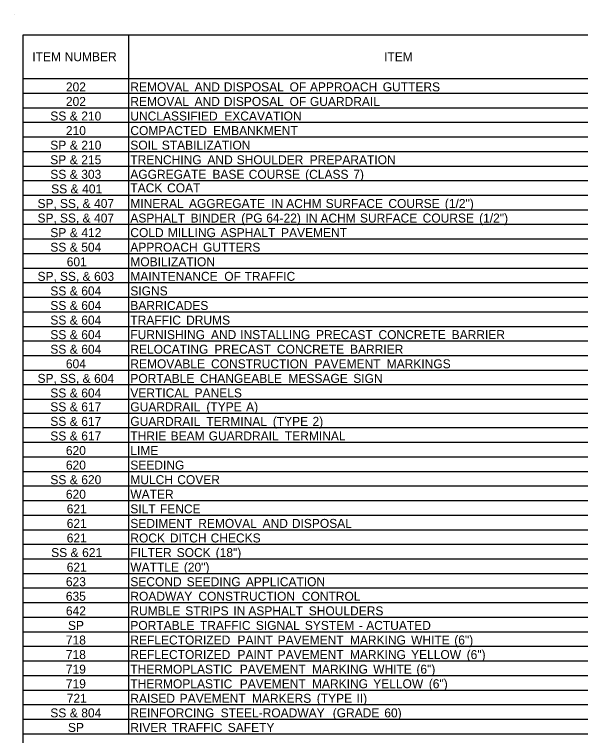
# Model space of a CAD drawing. Extents: x 544250 to 1930787, y -1948365 to 596640.
# Drawn here: x 557859.6 to 558238.2, y -1947939.8 to -1947457.4 of the extents above; entities that cross this region are included whole.
import ezdxf

# ---------------------------------------------------------------- set-up
doc = ezdxf.new("R2010")
doc.units = 0
doc.layers.add('Default', color=7, linetype='Continuous')

msp = doc.modelspace()

# ---------------------------------------------------------------- linework, layer by layer
at = {"layer": 'Default'}
for p, q in [((557859.63, -1947457.37), (557859.63, -1947457.37)), ((557865.48, -1947471.02), (558616.23, -1947471.02)), ((557865.48, -1948065.28), (557865.48, -1947471.02)), ((557865.48, -1948065.28), (557865.48, -1947471.02)), ((557936.17, -1947938.53), (557936.17, -1947471.02)), ((557865.48, -1947500.27), (558616.23, -1947500.27)), ((557865.48, -1947500.27), (558616.23, -1947500.27)), ((557936.17, -1947938.53), (557936.17, -1947500.27)), ((557865.48, -1947510.02), (558616.23, -1947510.02)), ((557865.48, -1947519.77), (558616.23, -1947519.77)), ((557865.48, -1947529.52), (558616.23, -1947529.52)), ((557865.48, -1947539.27), (558616.23, -1947539.27)), ((557865.48, -1947549.02), (558616.23, -1947549.02)), ((557865.48, -1947558.77), (558616.23, -1947558.77)), ((557865.48, -1947568.52), (558616.23, -1947568.52)), ((557865.48, -1947578.27), (558616.23, -1947578.27)), ((557865.48, -1947588.02), (558616.23, -1947588.02)), ((557865.48, -1947597.77), (558616.23, -1947597.77)), ((557865.48, -1947607.52), (558616.23, -1947607.52)), ((557865.48, -1947617.27), (558616.23, -1947617.27)), ((557865.48, -1947627.02), (558616.23, -1947627.02)), ((557865.48, -1947636.77), (558616.23, -1947636.77)), ((557865.48, -1947646.52), (558616.23, -1947646.52)), ((557865.48, -1947656.27), (558616.23, -1947656.27)), ((557865.48, -1947666.02), (558616.23, -1947666.02)), ((557865.48, -1947675.77), (558616.23, -1947675.77)), ((557865.48, -1947685.52), (558616.23, -1947685.52)), ((557865.48, -1947695.27), (558616.23, -1947695.27)), ((557865.48, -1947705.02), (558616.23, -1947705.02)), ((557865.48, -1947714.77), (558616.23, -1947714.77)), ((557865.48, -1947724.03), (558616.23, -1947724.03)), ((557865.48, -1947733.78), (558616.23, -1947733.78)), ((557865.48, -1947743.53), (558616.23, -1947743.53)), ((557865.48, -1947753.28), (558616.23, -1947753.28)), ((557865.48, -1947763.03), (558616.23, -1947763.03)), ((557865.48, -1947772.78), (558616.23, -1947772.78)), ((557865.48, -1947782.53), (558616.23, -1947782.53)), ((557865.48, -1947792.28), (558616.23, -1947792.28)), ((557865.48, -1947802.03), (558616.23, -1947802.03)), ((557865.48, -1947811.78), (558616.23, -1947811.78)), ((557865.48, -1947821.53), (558616.23, -1947821.53)), ((557865.48, -1947831.28), (558616.23, -1947831.28)), ((557865.48, -1947841.03), (558616.23, -1947841.03)), ((557865.48, -1947850.78), (558616.23, -1947850.78)), ((557865.48, -1947860.53), (558616.23, -1947860.53)), ((557865.48, -1947870.28), (558616.23, -1947870.28)), ((557865.48, -1947880.03), (558616.23, -1947880.03)), ((557865.48, -1947889.78), (558616.23, -1947889.78)), ((557865.48, -1947899.53), (558616.23, -1947899.53)), ((557865.48, -1947909.28), (558616.23, -1947909.28)), ((557865.48, -1947919.03), (558616.23, -1947919.03)), ((557865.48, -1947928.78), (558616.23, -1947928.78)), ((557865.48, -1947938.53), (558235.98, -1947938.53)), ((557865.48, -1947938.53), (558616.23, -1947938.53)), ((558235.98, -1947938.53), (558296.92, -1947938.53))]:
    msp.add_line(p, q, dxfattribs=at)

# ---------------------------------------------------------------- texts
for s, p in [('ITEM', (557871.57, -1947488.64)), (' NUMBER', (557891, -1947488.64)), ('ITEM', (558106.83, -1947488.64)), ('202', (557894.06, -1947508.82)), ('REMOVAL', (557937.14, -1947508.82)), (' AND', (557977.85, -1947508.82)), (' DISPOSAL', (557997.43, -1947508.82)), (' OF', (558041.39, -1947508.82)), (' APPROACH', (558054.98, -1947508.82)), (' GUTTERS', (558103.69, -1947508.82)), ('202', (557894.06, -1947518.57)), ('REMOVAL', (557937.14, -1947518.57)), (' AND', (557977.85, -1947518.57)), (' DISPOSAL', (557997.43, -1947518.57)), (' OF', (558041.39, -1947518.57)), (' GUARDRAIL', (558054.98, -1947518.57)), ('SS', (557883.64, -1947528.32)), (' &', (557894.38, -1947528.32)), (' 210', (557902.11, -1947528.32)), ('UNCLASSIFIED', (557937.14, -1947528.32)), (' EXCAVATION', (557997.73, -1947528.32)), ('210', (557894.04, -1947538.07)), ('COMPACTED', (557937.14, -1947538.07)), (' EMBANKMENT', (557990.27, -1947538.07)), ('SP', (557883.6, -1947547.82)), (' &', (557894.42, -1947547.82)), (' 210', (557902.15, -1947547.82)), ('SOIL', (557937.14, -1947547.82)), (' STABILIZATION', (557955.95, -1947547.82)), ('SP', (557883.56, -1947557.57)), (' &', (557894.38, -1947557.57)), (' 215', (557902.11, -1947557.57)), ('TRENCHING', (557937.14, -1947557.57)), (' AND', (557986.46, -1947557.57)), (' SHOULDER', (558006.04, -1947557.57)), (' PREPARATION', (558054.84, -1947557.57)), ('SS', (557883.62, -1947567.32)), (' &', (557894.37, -1947567.32)), (' 303', (557902.1, -1947567.32)), ('AGGREGATE', (557937.14, -1947567.32)), (' BASE', (557989.81, -1947567.32)), (' COURSE', (558014.06, -1947567.32)), (' (CLASS', (558051.81, -1947567.32)), (' 7)', (558083.98, -1947567.32)), ('SS', (557884.2, -1947577.07)), (' &', (557894.95, -1947577.07)), (' 401', (557902.68, -1947577.07)), ('TACK', (557937.14, -1947576.39)), (' COAT', (557959.49, -1947576.39)), ('SP,', (557875.07, -1947586.82)), (' SS,', (557887.83, -1947586.82)), (' &', (557902.93, -1947586.82)), (' 407', (557910.66, -1947586.82)), ('MINERAL', (557937.14, -1947586.82)), (' AGGREGATE', (557974.11, -1947586.82)), (' IN', (558029.11, -1947586.82)), (' ACHM', (558039.13, -1947586.82)), (' SURFACE', (558065.51, -1947586.82)), (' COURSE', (558107.46, -1947586.82)), (' (1/2")', (558145.21, -1947586.82)), ('SP,', (557875.07, -1947596.57)), (' SS,', (557887.83, -1947596.57)), (' &', (557902.93, -1947596.57)), (' 407', (557910.66, -1947596.57)), ('ASPHALT', (557937.14, -1947596.57)), (' BINDER', (557975.18, -1947596.57)), (' (PG', (558009.08, -1947596.57)), (' 64-22)', (558025.78, -1947596.57)), (' IN', (558052.03, -1947596.57)), (' ACHM', (558062.05, -1947596.57)), (' SURFACE', (558088.43, -1947596.57)), (' COURSE', (558130.38, -1947596.57)), (' (1/2")', (558168.13, -1947596.57)), ('SP', (557883.62, -1947606.32)), (' &', (557894.44, -1947606.32)), (' 412', (557902.17, -1947606.32)), ('COLD', (557937.14, -1947606.32)), (' MILLING', (557959.99, -1947606.32)), (' ASPHALT', (557995.32, -1947606.32)), (' PAVEMENT', (558035.69, -1947606.32)), ('SS', (557883.64, -1947616.07)), (' &', (557894.38, -1947616.07)), (' 504', (557902.11, -1947616.07)), ('APPROACH', (557937.14, -1947616.07)), (' GUTTERS', (557983.53, -1947616.07)), ('601', (557894.61, -1947625.82)), ('MOBILIZATION', (557937.14, -1947625.82)), ('SP,', (557875.07, -1947635.57)), (' SS,', (557887.83, -1947635.57)), (' &', (557902.93, -1947635.57)), (' 603', (557910.66, -1947635.57)), ('MAINTENANCE', (557937.14, -1947635.57)), (' OF', (557997.72, -1947635.57)), (' TRAFFIC', (558011.31, -1947635.57)), ('SS', (557883.64, -1947645.32)), (' &', (557894.38, -1947645.32)), (' 604', (557902.11, -1947645.32)), ('SIGNS', (557937.14, -1947645.32)), ('SS', (557883.64, -1947655.07)), (' &', (557894.38, -1947655.07)), (' 604', (557902.11, -1947655.07)), ('BARRICADES', (557937.14, -1947655.07)), ('SS', (557883.64, -1947664.82)), (' &', (557894.38, -1947664.82)), (' 604', (557902.11, -1947664.82)), ('TRAFFIC', (557937.14, -1947664.82)), (' DRUMS', (557972.21, -1947664.82)), ('SS', (557883.64, -1947674.57)), (' &', (557894.38, -1947674.57)), (' 604', (557902.11, -1947674.57)), ('FURNISHING', (557937.14, -1947674.57)), (' AND', (557988.79, -1947674.57)), (' INSTALLING', (558008.37, -1947674.57)), (' PRECAST', (558059.08, -1947674.57)), (' CONCRETE', (558100.85, -1947674.57)), (' BARRIER', (558149.77, -1947674.57)), ('SS', (557883.64, -1947684.32)), (' &', (557894.38, -1947684.32)), (' 604', (557902.11, -1947684.32)), ('RELOCATING', (557937.14, -1947684.32)), (' PRECAST', (557991.12, -1947684.32)), (' CONCRETE', (558032.88, -1947684.32)), (' BARRIER', (558081.81, -1947684.32)), ('604', (557894.04, -1947694.07)), ('REMOVABLE', (557937.14, -1947694.07)), (' CONSTRUCTION', (557988.88, -1947694.07)), (' PAVEMENT', (558058.06, -1947694.07)), (' MARKINGS', (558106.34, -1947694.07)), ('SP,', (557875.08, -1947703.82)), (' SS,', (557887.85, -1947703.82)), (' &', (557902.94, -1947703.82)), (' 604', (557910.67, -1947703.82)), ('PORTABLE', (557937.14, -1947703.82)), (' CHANGEABLE', (557981.43, -1947703.82)), (' MESSAGE', (558040.62, -1947703.82)), (' SIGN', (558083.97, -1947703.82)), ('SS', (557883.64, -1947713.57)), (' &', (557894.38, -1947713.57)), (' 604', (557902.11, -1947713.57)), ('VERTICAL', (557937.14, -1947713.57)), (' PANELS', (557977.85, -1947713.57)), ('SS', (557883.62, -1947722.83)), (' &', (557894.37, -1947722.83)), (' 617', (557902.1, -1947722.83)), ('GUARDRAIL', (557937.14, -1947722.83)), (' (TYPE', (557985.76, -1947722.83)), (' A)', (558012.33, -1947722.83)), ('SS', (557883.62, -1947732.58)), (' &', (557894.37, -1947732.58)), (' 617', (557902.1, -1947732.58)), ('GUARDRAIL', (557937.14, -1947732.58)), (' TERMINAL', (557985.76, -1947732.58)), (' (TYPE', (558030.18, -1947732.58)), (' 2)', (558056.75, -1947732.58)), ('SS', (557883.62, -1947742.33)), (' &', (557894.37, -1947742.33)), (' 617', (557902.1, -1947742.33)), ('THRIE', (557937.14, -1947742.33)), (' BEAM', (557961.85, -1947742.33)), (' GUARDRAIL', (557987.31, -1947742.33)), (' TERMINAL', (558038.25, -1947742.33)), ('620', (557894.04, -1947752.08)), ('LIME', (557937.14, -1947752.08)), ('620', (557894.04, -1947761.83)), ('SEEDING', (557937.14, -1947761.83)), ('SS', (557883.64, -1947771.58)), (' &', (557894.38, -1947771.58)), (' 620', (557902.11, -1947771.58)), ('MULCH', (557937.14, -1947771.58)), (' COVER', (557966.28, -1947771.58)), ('620', (557894.04, -1947781.33)), ('WATER', (557937.14, -1947781.33)), ('621', (557894.61, -1947791.08)), ('SILT', (557937.14, -1947791.08)), (' FENCE', (557954.68, -1947791.08)), ('621', (557894.61, -1947800.83)), ('SEDIMENT', (557937.14, -1947800.83)), (' REMOVAL', (557980.3, -1947800.83)), (' AND', (558023.33, -1947800.83)), (' DISPOSAL', (558042.91, -1947800.83)), ('621', (557894.61, -1947810.58)), ('ROCK', (557937.14, -1947810.58)), (' DITCH', (557961.35, -1947810.58)), (' CHECKS', (557988.62, -1947810.58)), ('SS', (557884.2, -1947820.33)), (' &', (557894.95, -1947820.33)), (' 621', (557902.68, -1947820.33)), ('FILTER', (557937.14, -1947820.33)), (' SOCK', (557965.91, -1947820.33)), (' (18")', (557991.98, -1947820.33)), ('621', (557894.61, -1947830.08)), ('WATTLE', (557937.14, -1947830.08)), (' (20")', (557970.7, -1947830.08)), ('623', (557894.03, -1947839.83)), ('SECOND', (557937.14, -1947839.83)), (' SEEDING', (557972.57, -1947839.83)), (' APPLICATION', (558012.11, -1947839.83)), ('635', (557894, -1947849.58)), ('ROADWAY', (557937.14, -1947849.58)), (' CONSTRUCTION', (557980.4, -1947849.58)), (' CONTROL', (558049.58, -1947849.58)), ('642', (557894.06, -1947859.33)), ('RUMBLE', (557937.14, -1947859.33)), (' STRIPS', (557971.64, -1947859.33)), (' IN', (558003.81, -1947859.33)), (' ASPHALT', (558013.83, -1947859.33)), (' SHOULDERS', (558054.2, -1947859.33)), ('SP', (557895.42, -1947869.08)), ('PORTABLE', (557937.14, -1947869.08)), (' TRAFFIC', (557981.43, -1947869.08)), (' SIGNAL', (558018.82, -1947869.08)), (' SYSTEM', (558051.6, -1947869.08)), (' ACTUATED', (558092.63, -1947869.08)), (' -', (558087.77, -1947869.08)), ('718', (557894.02, -1947878.83)), ('REFLECTORIZED', (557937.14, -1947878.83)), (' PAINT', (558006.57, -1947878.83)), (' PAVEMENT', (558033.42, -1947878.83)), (' MARKING', (558081.7, -1947878.83)), (' WHITE', (558122.63, -1947878.83)), (' (6")', (558151.52, -1947878.83)), ('718', (557894.02, -1947888.58)), ('REFLECTORIZED', (557937.14, -1947888.58)), (' PAINT', (558006.57, -1947888.58)), (' PAVEMENT', (558033.42, -1947888.58)), (' MARKING', (558081.7, -1947888.58)), (' YELLOW', (558122.63, -1947888.58)), (' (6")', (558159.8, -1947888.58)), ('719', (557894.02, -1947898.33)), ('THERMOPLASTIC', (557937.14, -1947898.33)), (' PAVEMENT', (558008.08, -1947898.33)), (' MARKING', (558056.37, -1947898.33)), (' WHITE', (558097.3, -1947898.33)), (' (6")', (558126.19, -1947898.33)), ('719', (557894.02, -1947908.08)), ('THERMOPLASTIC', (557937.14, -1947908.08)), (' MARKING', (558056.37, -1947908.08)), (' YELLOW', (558097.3, -1947908.08)), (' (6")', (558134.47, -1947908.08)), (' PAVEMENT', (558008.08, -1947908.08)), (' (TYPE', (558059.55, -1947917.83)), (' II)', (558086.12, -1947917.83)), ('721', (557894.61, -1947917.83)), ('RAISED', (557937.14, -1947917.83)), (' PAVEMENT', (557967.91, -1947917.83)), (' MARKERS', (558016.2, -1947917.83)), (' (GRADE', (558070.24, -1947927.58)), (' 60)', (558104.73, -1947927.58)), ('SS', (557883.64, -1947927.58)), (' &', (557894.38, -1947927.58)), (' 804', (557902.11, -1947927.58)), ('REINFORCING', (557937.14, -1947927.58)), (' STEEL-ROADWAY', (557995.31, -1947927.58)), ('SP', (557895.42, -1947937.33)), ('RIVER', (557937.14, -1947937.33)), (' TRAFFIC', (557962.65, -1947937.33)), (' SAFETY', (558000.04, -1947937.33))]:
    msp.add_text(s, height=6, dxfattribs=at).set_placement(p)

doc.saveas('drawing.dxf')
